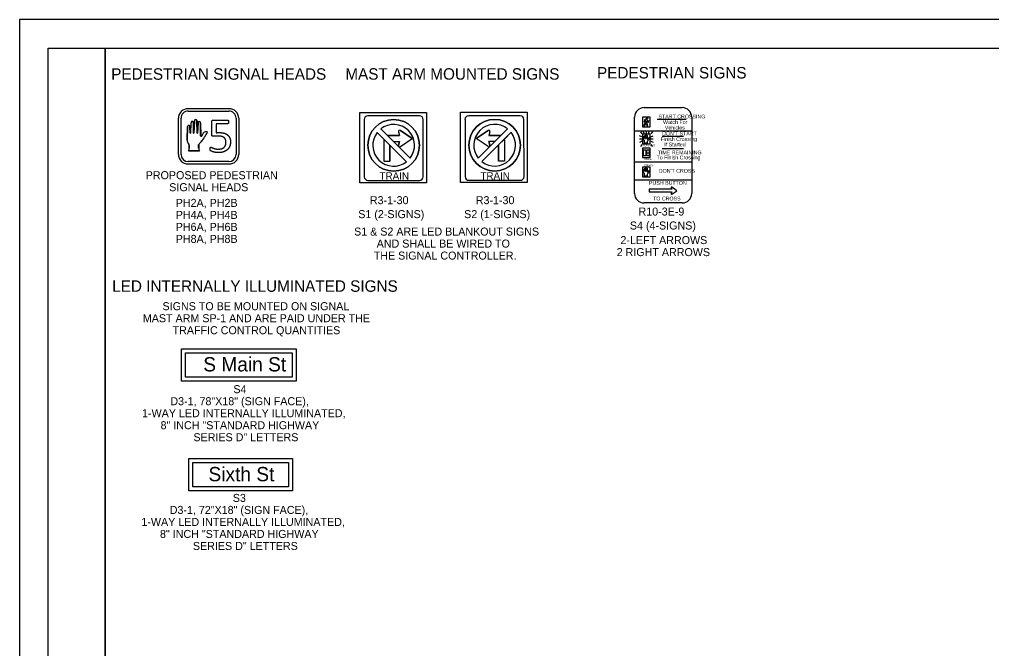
# Model space of a CAD drawing. Extents: x 0 to 34, y 0 to 22.
# Drawn here: x 0 to 17, y 11 to 22 of the extents above; entities that cross this region are included whole.
import ezdxf

# ---------------------------------------------------------------- set-up
doc = ezdxf.new("R2010")
doc.units = 0
for name, color, linetype in [('Default', 7, 'Continuous'), ('PM_P_Stop_Line', 7, 'Continuous'), ('SC_Scratch1', 7, 'Continuous'), ('SG_P_Conduit', 7, 'Continuous'), ('SG_P_Detection', 7, 'Continuous'), ('SG_P_Heads', 7, 'Continuous'), ('UT_X_Electric', 7, 'Continuous')]:
    doc.layers.add(name, color=color, linetype=linetype)

# ---------------------------------------------------------------- blocks, each defined once
blk = doc.blocks.new('HAND')
at = {"layer": 'Default'}
for points in [[(0.0005, 0.1047), (0.0004, 0.1045), (0.004, 0.1776), (0.004, 0.1776)], [(0.0186, 0.1776), (0.0186, 0.1776), (0.0199, 0.105), (0.0199, 0.105)], [(-0.0387, 0.0626), (-0.0387, 0.0626), (-0.0372, 0.143), (-0.0372, 0.143)], [(-0.0227, 0.143), (-0.0227, 0.143), (-0.0215, 0.105), (-0.0215, 0.105)], [(-0.0196, 0.1047), (-0.0197, 0.1045), (-0.0167, 0.1665), (-0.0167, 0.1665)], [(-0.0022, 0.1665), (-0.0022, 0.1665), (-0.0014, 0.105), (-0.0014, 0.105)], [(0.0218, 0.1047), (0.0218, 0.1045), (0.0247, 0.1659), (0.0247, 0.1659)], [(0.0392, 0.1659), (0.0392, 0.1659), (0.0402, 0.0888), (0.0402, 0.0888)], [(0.0477, 0.089), (0.0477, 0.089)], [(-0.032, 0.0432), (-0.032, 0.0432)], [(-0.0271, 0.0154), (-0.0271, 0.0154), (-0.0271, 0.0308), (-0.0271, 0.0308)], [(0.0284, 0.0364), (0.0284, 0.0364), (0.0284, 0.0154), (0.0284, 0.0154)], [(0.0327, -0.0008), (-0.0313, -0.0008), (-0.0313, -0.0008)], [(0.0327, -0.0008), (0.0327, -0.0008)]]:
    blk.add_lwpolyline(points, dxfattribs=at)
for centre, radius, start, end in [((-0.0094, 0.1665), 0.00726, 0, 180), ((0.0113, 0.1776), 0.00726, 0, 180), ((0.032, 0.1659), 0.00726, 0, 180), ((-0.03, 0.143), 0.00726, 0, 180), ((-0.011, 0.0613), 0.0278, 177.3964, 220.6574), ((-0.0206, 0.1048), 0.000943, 167.1401, 358.6099), ((-0.0005, 0.1048), 0.000943, 167.1401, 358.6099), ((0.0208, 0.1048), 0.000943, 167.1401, 358.6099), ((0.0439, 0.0907), 0.00414, 208.0703, 335.996), ((-0.1141, 0.1925), 0.2098, 318.2058, 337.3712), ((0.078, 0.0836), 0.0308, 107.2466, 169.8826), ((0.073, 0.1019), 0.0119, 56.229, 110.2726), ((-0.0476, 0.0298), 0.0205, 2.7749, 40.7212), ((-0.0593, 0.0151), 0.0322, 330.2887, 0.5181), ((0.0742, 0.0112), 0.0523, 127.5194, 151.0809), ((0.0606, 0.0151), 0.0322, 179.4819, 209.7113)]:
    blk.add_arc(centre, radius, start, end, dxfattribs=at)

msp = doc.modelspace()

# ---------------------------------------------------------------- linework, layer by layer
at = {"layer": 'PM_P_Stop_Line'}
for points in [[(0.5, 21.5), (1.5, 21.5), (1.5, 0.5), (0.5, 0.5)], [(1.5, 21.5), (33.5, 21.5), (33.5, 0.5), (1.5, 0.5)]]:
    msp.add_lwpolyline(points, close=True, dxfattribs=at)
at = {"layer": 'SC_Scratch1'}
for p, q in [((8.194, 20.06), (7.989, 19.919)), ((6.458, 19.971), (6.648, 19.971)), ((6.628, 20.034), (6.648, 19.971)), ((6.661, 20.058), (6.866, 19.917)), ((6.661, 19.776), (6.866, 19.917)), ((8.194, 19.778), (7.989, 19.919)), ((8.227, 20.036), (8.207, 19.973)), ((8.397, 19.973), (8.207, 19.973)), ((6.372, 19.885), (6.372, 19.52)), ((6.48, 19.803), (6.48, 19.52)), ((6.54, 19.863), (6.648, 19.863)), ((6.628, 19.8), (6.648, 19.863)), ((8.315, 19.866), (8.207, 19.866)), ((8.227, 19.802), (8.207, 19.866)), ((8.375, 19.805), (8.375, 19.522)), ((8.483, 19.887), (8.483, 19.522)), ((6.372, 19.52), (6.48, 19.52))]:
    msp.add_line(p, q, dxfattribs=at)
for points in [[(5.95, 20.375), (7.117, 20.375), (7.117, 19.144), (5.95, 19.144)], [(7.713, 20.377), (8.88, 20.377), (8.88, 19.147), (7.713, 19.147)], [(2.836, 16.242), (4.842, 16.242), (4.842, 15.677), (2.836, 15.677)], [(2.906, 16.172), (4.772, 16.172), (4.772, 15.747), (2.906, 15.747)], [(2.963, 14.323), (4.777, 14.323), (4.777, 13.758), (2.963, 13.758)], [(3.033, 14.253), (4.707, 14.253), (4.707, 13.828), (3.033, 13.828)]]:
    msp.add_lwpolyline(points, close=True, dxfattribs=at)
for points in [[(6.029, 20.25), (6.03, 19.25)], [(6.995, 20.314), (6.093, 20.314)], [(7.061, 19.25), (7.059, 20.25)], [(7.792, 20.252), (7.793, 19.252)], [(8.758, 20.317), (7.856, 20.317)], [(8.824, 19.252), (8.823, 20.252)], [(8.194, 19.778), (7.989, 19.919), (8.194, 20.06)], [(6.48, 19.803), (6.375, 19.907)], [(6.436, 19.968), (6.54, 19.863), (6.648, 19.863), (6.628, 19.8)], [(6.628, 20.034), (6.648, 19.971), (6.458, 19.971)], [(6.661, 19.776), (6.866, 19.917), (6.661, 20.058)], [(8.227, 20.036), (8.207, 19.973), (8.397, 19.973)], [(8.419, 19.97), (8.315, 19.866), (8.207, 19.866), (8.227, 19.802)], [(8.375, 19.805), (8.48, 19.909)], [(6.372, 19.885), (6.372, 19.52), (6.48, 19.52), (6.48, 19.803)], [(8.483, 19.887), (8.483, 19.522), (8.375, 19.522), (8.375, 19.805)], [(6.095, 19.185), (6.996, 19.185)], [(7.858, 19.187), (8.76, 19.187)]]:
    msp.add_lwpolyline(points, dxfattribs=at)
for centre, radius, start, end in [((6.093, 20.25), 0.0644, 90, 180), ((6.995, 20.25), 0.0644, 0, 90), ((7.856, 20.252), 0.0644, 90, 180), ((8.758, 20.252), 0.0644, 0, 90), ((6.649, 20.041), 0.0215, 55.4837, 197.3618), ((6.649, 20.041), 0.0215, 55.4837, 197.3618), ((8.206, 20.043), 0.0215, 342.6382, 124.5163), ((8.206, 20.043), 0.0215, 342.6382, 124.5163), ((6.458, 19.885), 0.0859, 165, 180), ((6.458, 19.885), 0.0859, 165, 180), ((6.458, 19.885), 0.0859, 90, 105), ((6.458, 19.885), 0.0859, 90, 105), ((8.397, 19.887), 0.0859, 75, 90), ((8.397, 19.887), 0.0859, 75, 90), ((8.397, 19.887), 0.0859, 360, 15), ((8.397, 19.887), 0.0859, 360, 15), ((6.649, 19.794), 0.0215, 162.6382, 304.5163), ((6.649, 19.794), 0.0215, 162.6382, 304.5163), ((8.206, 19.796), 0.0215, 235.4837, 17.3618), ((8.206, 19.796), 0.0215, 235.4837, 17.3618), ((6.095, 19.25), 0.0644, 180, 270), ((6.996, 19.25), 0.0644, 270, 0), ((7.858, 19.252), 0.0644, 180, 270), ((8.76, 19.252), 0.0644, 270, 0)]:
    msp.add_arc(centre, radius, start, end, dxfattribs=at)
at = {"layer": 'SG_P_Conduit'}
for p, q in [((10.928, 20.244), (10.925, 20.209)), ((10.933, 20.209), (10.937, 20.239)), ((10.937, 20.239), (10.946, 20.239)), ((10.946, 20.239), (10.941, 20.223)), ((10.983, 20.231), (10.983, 20.231)), ((11.007, 20.213), (10.983, 20.231)), ((11.155, 20.255), (11.657, 20.255)), ((10.942, 20.202), (10.921, 20.14)), ((10.921, 20.14), (10.931, 20.132)), ((10.925, 20.209), (10.933, 20.209)), ((10.931, 20.132), (10.955, 20.186)), ((10.941, 20.204), (10.942, 20.202)), ((10.955, 20.186), (10.964, 20.175)), ((10.964, 20.175), (10.976, 20.133)), ((10.966, 20.211), (10.973, 20.227)), ((10.971, 20.2), (10.966, 20.211)), ((10.978, 20.184), (10.971, 20.2)), ((10.973, 20.227), (10.979, 20.217)), ((10.976, 20.133), (10.988, 20.139)), ((10.988, 20.139), (10.978, 20.184)), ((10.979, 20.217), (11.002, 20.206)), ((11.002, 20.206), (11.007, 20.213)), ((6.257, 20.025), (6.77, 19.512)), ((8.598, 20.027), (8.085, 19.514)), ((10.757, 20.055), (11.757, 20.055)), ((10.885, 19.946), (10.845, 19.965)), ((10.885, 19.909), (10.845, 19.909)), ((10.858, 20.037), (10.886, 20.002)), ((10.91, 20.042), (10.926, 20.002)), ((10.922, 19.887), (10.924, 19.96)), ((10.933, 19.96), (10.935, 19.921)), ((10.935, 19.921), (10.939, 19.921)), ((10.939, 19.921), (10.94, 19.973)), ((10.95, 19.973), (10.95, 19.921)), ((10.95, 19.921), (10.953, 19.921)), ((10.953, 19.921), (10.955, 19.98)), ((10.964, 20.002), (10.964, 20.042)), ((10.966, 19.98), (10.966, 19.921)), ((10.966, 19.921), (10.97, 19.921)), ((10.97, 19.921), (10.971, 19.972)), ((10.98, 19.973), (10.983, 19.904)), ((10.989, 19.904), (11.001, 19.922)), ((11, 20.002), (11.015, 20.042)), ((11.069, 20.037), (11.041, 20.002)), ((11.042, 19.945), (11.082, 19.963)), ((11.082, 19.909), (11.042, 19.909)), ((11.241, 19.959), (11.615, 19.959)), ((10.885, 19.87), (10.845, 19.851)), ((10.885, 19.813), (10.858, 19.781)), ((10.979, 19.836), (10.93, 19.836)), ((10.933, 19.842), (10.933, 19.866)), ((10.975, 19.864), (10.975, 19.843)), ((11.042, 19.872), (11.082, 19.853)), ((11.042, 19.813), (11.069, 19.781)), ((11.241, 19.742), (11.615, 19.742)), ((10.973, 19.669), (11.013, 19.669)), ((10.757, 19.513), (11.757, 19.513)), ((10.922, 19.311), (10.924, 19.384)), ((10.933, 19.384), (10.935, 19.346)), ((10.939, 19.346), (10.94, 19.397)), ((10.95, 19.397), (10.95, 19.346)), ((10.953, 19.346), (10.955, 19.404)), ((10.966, 19.404), (10.966, 19.346)), ((10.97, 19.346), (10.971, 19.397)), ((10.98, 19.397), (10.983, 19.329)), ((10.979, 19.26), (10.93, 19.26)), ((10.933, 19.266), (10.933, 19.291)), ((10.935, 19.346), (10.939, 19.346)), ((10.95, 19.346), (10.953, 19.346)), ((10.966, 19.346), (10.97, 19.346)), ((10.975, 19.289), (10.975, 19.268)), ((10.989, 19.328), (11.001, 19.347)), ((10.757, 19.194), (11.757, 19.194)), ((11.397, 19.058), (11.406, 19.03)), ((11.499, 19.006), (11.411, 19.068)), ((11.405, 19.03), (11.015, 19.03)), ((11.015, 19.03), (11.015, 18.983)), ((11.257, 19.006), (11.257, 19.006)), ((11.406, 18.983), (11.397, 18.954)), ((11.406, 19.03), (11.405, 19.03)), ((11.411, 18.944), (11.499, 19.006))]:
    msp.add_line(p, q, dxfattribs=at)
for points in [[(10.924, 20.458), (11.59, 20.458)], [(10.757, 18.958), (10.757, 20.291)], [(11.757, 20.291), (11.757, 18.958)], [(6.436, 19.968), (6.318, 20.086)], [(8.419, 19.97), (8.537, 20.088)], [(6.257, 20.025), (6.375, 19.907)], [(6.375, 19.907), (6.48, 19.803), (6.77, 19.512)], [(6.831, 19.573), (6.54, 19.863), (6.436, 19.968)], [(8.024, 19.575), (8.315, 19.866), (8.419, 19.97)], [(8.48, 19.909), (8.375, 19.805), (8.085, 19.514)], [(8.598, 20.027), (8.48, 19.909)], [(11.018, 19.927), (11.008, 19.908), (11, 19.894)], [(11.018, 19.352), (11.008, 19.332), (11, 19.319)], [(11.015, 18.983), (11.405, 18.983)], [(11.59, 18.791), (10.924, 18.791)]]:
    msp.add_lwpolyline(points, dxfattribs=at)
for points in [[(10.895, 20.124), (11.032, 20.124), (11.032, 20.291), (10.895, 20.291)], [(10.895, 19.826), (11.032, 19.826), (11.032, 19.992), (10.895, 19.992)], [(10.895, 19.584), (11.032, 19.584), (11.032, 19.751), (10.895, 19.751)], [(10.912, 19.723), (10.952, 19.723), (10.952, 19.615), (10.912, 19.615)], [(10.973, 19.723), (11.013, 19.723), (11.013, 19.615), (10.973, 19.615)], [(10.895, 19.25), (11.032, 19.25), (11.032, 19.417), (10.895, 19.417)]]:
    msp.add_lwpolyline(points, close=True, dxfattribs=at)
for centre, radius in [((6.544, 19.799), 0.451), ((8.311, 19.801), 0.451), ((10.976, 20.271), 0.0103)]:
    msp.add_circle(centre, radius, dxfattribs=at)
for centre, radius, start, end in [((10.924, 20.291), 0.167, 90, 180), ((11.59, 20.291), 0.167, 0, 90), ((6.544, 19.799), 0.451, 0, 180), ((8.311, 19.801), 0.451, 360, 180), ((6.544, 19.799), 0.365, 321.7563, 128.2437), ((6.544, 19.799), 0.365, 321.7563, 128.2437), ((8.311, 19.801), 0.365, 51.7563, 218.2437), ((8.311, 19.801), 0.365, 51.7563, 218.2437), ((6.544, 19.799), 0.365, 141.7563, 308.2437), ((6.544, 19.799), 0.365, 141.7563, 308.2437), ((8.311, 19.801), 0.365, 231.7563, 38.2437), ((8.311, 19.801), 0.365, 231.7563, 38.2437), ((10.929, 19.958), 0.00491, 17.2617, 162.7383), ((10.945, 19.972), 0.00492, 8.2338, 172.7854), ((10.96, 19.979), 0.00538, 14.8098, 166.7635), ((10.975, 19.972), 0.00484, 7.5404, 176.7973), ((10.986, 19.906), 0.00319, 202.4359, 334.4764), ((10.961, 19.916), 0.0451, 307.7756, 331.4618), ((11.011, 19.916), 0.012, 86.7688, 149.658), ((11.012, 19.904), 0.0246, 76.4727, 90.8564), ((6.544, 19.799), 0.451, 180, 0), ((8.311, 19.801), 0.451, 180, 360), ((10.934, 19.886), 0.0115, 175.876, 235.3646), ((10.917, 19.864), 0.0162, 6.5622, 49.5415), ((10.922, 19.844), 0.0104, 311.3432, 350.588), ((11.001, 19.856), 0.0266, 117.1684, 162.5699), ((10.986, 19.844), 0.011, 181.2383, 225.3799), ((10.929, 19.383), 0.00491, 17.2617, 162.7383), ((10.945, 19.397), 0.00492, 8.2338, 172.7854), ((10.96, 19.403), 0.00538, 14.8098, 166.7635), ((10.975, 19.397), 0.00484, 7.5404, 176.7973), ((10.934, 19.311), 0.0115, 175.876, 235.3646), ((10.917, 19.289), 0.0162, 6.5622, 49.5415), ((10.922, 19.268), 0.0104, 311.3432, 350.588), ((11.001, 19.281), 0.0266, 117.1684, 162.5699), ((10.986, 19.268), 0.011, 181.2383, 225.3799), ((10.986, 19.33), 0.00319, 202.4359, 334.4764), ((10.961, 19.34), 0.0451, 307.7756, 331.4618), ((11.011, 19.341), 0.012, 86.7688, 149.658), ((11.012, 19.328), 0.0246, 76.4727, 90.8564), ((11.405, 19.061), 0.00912, 54.9207, 197.6378), ((10.924, 18.958), 0.167, 180, 270), ((11.405, 18.951), 0.00912, 162.3622, 305.0792), ((11.59, 18.958), 0.167, 270, 0)]:
    msp.add_arc(centre, radius, start, end, dxfattribs=at)
for points in [[(10.971, 20.259), (10.971, 20.259), (10.968, 20.259), (10.965, 20.259), (10.963, 20.259), (10.961, 20.259), (10.956, 20.256), (10.939, 20.249), (10.928, 20.244)], [(10.946, 20.239), (10.944, 20.234), (10.942, 20.228), (10.94, 20.22), (10.939, 20.214), (10.938, 20.209), (10.94, 20.206), (10.941, 20.204)], [(10.983, 20.231), (10.982, 20.238), (10.979, 20.245), (10.977, 20.253), (10.972, 20.258), (10.971, 20.259)]]:
    msp.add_open_spline(points, degree=3, dxfattribs=at)
at = {"layer": 'SG_P_Detection'}
for p, q in [((2.949, 20.44), (3.665, 20.44)), ((2.78, 19.641), (2.78, 20.271)), ((2.826, 19.641), (2.826, 20.271)), ((2.953, 20.397), (3.661, 20.397)), ((3.39, 20.241), (3.64, 20.241)), ((3.788, 20.271), (3.788, 19.641)), ((3.834, 20.271), (3.834, 19.641)), ((3.364, 19.984), (3.364, 20.212)), ((3.691, 19.86), (3.691, 19.86)), ((3.665, 19.472), (2.949, 19.472)), ((3.661, 19.515), (2.953, 19.515))]:
    msp.add_line(p, q, dxfattribs=at)
for points in [[(2.939, 20.125), (2.935, 19.888)], [(2.986, 20.013), (2.982, 20.125), (2.982, 20.125)], [(3, 20.195), (2.991, 20.012), (2.991, 20.012)], [(3.046, 20.013), (3.043, 20.195), (3.043, 20.195)], [(3.062, 20.227), (3.051, 20.012), (3.051, 20.012)], [(3.109, 20.013), (3.105, 20.227)], [(3.123, 20.193), (3.114, 20.012), (3.114, 20.012)], [(3.169, 19.965), (3.166, 20.193)], [(3.64, 20.176), (3.439, 20.176), (3.439, 20.018)], [(2.991, 20.012), (2.991, 20.012), (2.991, 20.012)], [(3.051, 20.012), (3.051, 20.012), (3.051, 20.012)], [(3.114, 20.012), (3.114, 20.012), (3.114, 20.012)], [(3.191, 19.966), (3.191, 19.966)], [(2.955, 19.83), (2.955, 19.831)], [(2.969, 19.794), (2.969, 19.748)], [(3.134, 19.748), (3.134, 19.811)], [(2.957, 19.7), (3.147, 19.7)]]:
    msp.add_lwpolyline(points, dxfattribs=at)
for centre, major_axis, start_param, end_param in [((2.949, 20.271), (0.169, 0), 1.570796, 3.141593), ((3.665, 20.271), (0.169, 0), 6.283185, 7.853982), ((2.953, 20.271), (0.127, 0), 1.570796, 3.141593), ((3.083, 20.227), (0.0215, 0), 6.283185, 9.424778), ((3.661, 20.271), (0.127, 0), 6.283185, 7.853982), ((2.961, 20.125), (0.0215, 0), 0, 3.141593), ((3.022, 20.195), (0.0215, 0), 0, 3.141593), ((3.145, 20.193), (0.0215, 0), 0, 3.141593), ((2.989, 20.012), (0.0028, 0), 2.917145, 6.054008), ((2.989, 20.012), (0.0028, 0), 6.061637, 6.258923), ((3.048, 20.012), (0.0028, 0), 2.917145, 6.049226), ((3.048, 20.012), (0.0028, 0), 6.126272, 6.258923), ((3.112, 20.012), (0.0028, 0), 2.917145, 6.058743), ((3.112, 20.012), (0.0028, 0), 6.099269, 6.258923), ((3.18, 19.971), (0.0123, 0), 3.631512, 5.864236), ((2.711, 20.271), (0.623, 0), 5.553739, 5.888238), ((3.281, 19.95), (0.0914, 0), 1.871807, 2.965011), ((3.266, 20.004), (0.0353, 0), 0.981382, 1.92462), ((3.017, 19.884), (0.0825, 0), 3.096152, 3.851198), ((2.909, 19.791), (0.0609, 0), 0.048431, 0.710719), ((2.874, 19.748), (0.0956, 0), 5.764626, 6.292228), ((3.27, 19.736), (0.155, 0), 2.225634, 2.636859), ((3.23, 19.748), (0.0956, 0), 3.13255, 3.660152), ((2.949, 19.641), (0.169, 0), 3.141593, 4.712389), ((2.953, 19.641), (0.127, 0), 3.141593, 4.712389), ((3.661, 19.641), (0.127, 0), 4.712389, 6.283185), ((3.665, 19.641), (0.169, 0), 4.712389, 6.283185)]:
    msp.add_ellipse(centre, major_axis=major_axis, ratio=0.995332, start_param=start_param, end_param=end_param, dxfattribs=at)
for points in [[(3.364, 20.212), (3.364, 20.227), (3.371, 20.234)], [(3.371, 20.234), (3.378, 20.241), (3.39, 20.241)], [(3.64, 20.241), (3.643, 20.241), (3.646, 20.239)], [(3.646, 20.239), (3.65, 20.237), (3.652, 20.233)], [(3.652, 20.233), (3.654, 20.229), (3.655, 20.223)], [(3.652, 20.184), (3.648, 20.176), (3.64, 20.176)], [(3.656, 20.209), (3.656, 20.193), (3.652, 20.184)], [(3.655, 20.223), (3.656, 20.217), (3.656, 20.209)], [(3.37, 19.962), (3.364, 19.968), (3.364, 19.984)], [(3.387, 19.957), (3.375, 19.957), (3.37, 19.962)], [(3.423, 19.959), (3.404, 19.957), (3.387, 19.957)], [(3.468, 19.962), (3.442, 19.962), (3.423, 19.959)], [(3.439, 20.018), (3.454, 20.02), (3.469, 20.021)], [(3.533, 19.955), (3.506, 19.962), (3.468, 19.962)], [(3.469, 20.021), (3.485, 20.021), (3.505, 20.021)], [(3.505, 20.021), (3.551, 20.021), (3.586, 20.01)], [(3.577, 19.935), (3.56, 19.948), (3.533, 19.955)], [(3.604, 19.9), (3.595, 19.921), (3.577, 19.935)], [(3.586, 20.01), (3.621, 19.998), (3.644, 19.977)], [(3.612, 19.853), (3.612, 19.88), (3.604, 19.9)], [(3.644, 19.977), (3.667, 19.956), (3.679, 19.926)], [(3.679, 19.926), (3.691, 19.896), (3.691, 19.86)], [(3.336, 19.751), (3.337, 19.757), (3.339, 19.76)], [(3.336, 19.738), (3.336, 19.745), (3.336, 19.751)], [(3.336, 19.724), (3.336, 19.73), (3.336, 19.738)], [(3.338, 19.715), (3.336, 19.718), (3.336, 19.724)], [(3.339, 19.76), (3.34, 19.764), (3.343, 19.766)], [(3.343, 19.766), (3.345, 19.767), (3.348, 19.767)], [(3.348, 19.767), (3.353, 19.767), (3.362, 19.762)], [(3.362, 19.762), (3.371, 19.757), (3.386, 19.75)], [(3.386, 19.75), (3.402, 19.744), (3.425, 19.738)], [(3.425, 19.738), (3.448, 19.733), (3.479, 19.733)], [(3.479, 19.733), (3.508, 19.733), (3.532, 19.739)], [(3.532, 19.739), (3.557, 19.746), (3.574, 19.761)], [(3.633, 19.72), (3.605, 19.696), (3.567, 19.684)], [(3.574, 19.761), (3.592, 19.776), (3.602, 19.798)], [(3.602, 19.798), (3.612, 19.821), (3.612, 19.853)], [(3.676, 19.78), (3.661, 19.744), (3.633, 19.72)], [(3.691, 19.86), (3.691, 19.815), (3.676, 19.78)], [(3.34, 19.708), (3.339, 19.711), (3.338, 19.715)], [(3.345, 19.703), (3.341, 19.706), (3.34, 19.708)], [(3.36, 19.695), (3.348, 19.7), (3.345, 19.703)], [(3.39, 19.684), (3.371, 19.689), (3.36, 19.695)], [(3.431, 19.675), (3.408, 19.679), (3.39, 19.684)], [(3.481, 19.671), (3.455, 19.671), (3.431, 19.675)], [(3.567, 19.684), (3.528, 19.671), (3.481, 19.671)]]:
    msp.add_open_spline(points, degree=2, dxfattribs=at)
at = {"layer": 'SG_P_Heads'}
msp.add_lwpolyline([(0, 0), (34, 0), (34, 22), (0, 22)], close=True, dxfattribs=at)

# ---------------------------------------------------------------- block references
at = {"layer": 'SG_P_Detection', "xscale": 2.9676009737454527, "yscale": 2.953749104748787, "rotation": -4.08392135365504e-09}
msp.add_blockref('HAND', (3.05, 19.703), dxfattribs=at)

# ---------------------------------------------------------------- texts
at = {"layer": 'SC_Scratch1'}
for s, height, p in [('TRAIN', 0.1288, (6.297, 19.198)), ('TRAIN', 0.1288, (8.061, 19.2)), ('SIGNS TO BE MOUNTED ON SIGNAL ', 0.14, (2.502, 16.916)), ('MAST ARM SP-1 AND ARE PAID UNDER THE ', 0.14, (2.158, 16.706)), ('TRAFFIC CONTROL QUANTITIES', 0.14, (2.678, 16.496)), ('S Main St', 0.25, (3.215, 15.845)), ('S4', 0.14, (3.741, 15.465)), ('D3-1, 78"X18" (SIGN FACE),', 0.14, (2.639, 15.255)), ('1-WAY LED INTERNALLY ILLUMINATED, ', 0.14, (2.144, 15.045)), ('8" INCH "STANDARD HIGHWAY', 0.14, (2.468, 14.835)), (' SERIES D" LETTERS', 0.14, (2.991, 14.625)), ('Sixth St', 0.25, (3.306, 13.925)), ('S3', 0.14, (3.731, 13.564)), ('D3-1, 72"X18" (SIGN FACE),', 0.14, (2.628, 13.354)), ('1-WAY LED INTERNALLY ILLUMINATED, ', 0.14, (2.133, 13.144)), ('8" INCH "STANDARD HIGHWAY', 0.14, (2.458, 12.934)), (' SERIES D" LETTERS', 0.14, (2.981, 12.724))]:
    msp.add_text(s, height=height, dxfattribs=at).set_placement(p)
at = {"layer": 'SG_P_Conduit'}
for s, height, p in [('START CROSSING', 0.06667, (11.176, 20.269)), ('Watch For', 0.0667, (11.255, 20.172)), ('Vehicles', 0.0667, (11.287, 20.075)), ('Finish Crossing', 0.06667, (11.213, 19.874)), ("DON'T START", 0.06667, (11.24, 19.973)), ('FLASHING', 0.0311, (10.903, 19.784)), ('If Started', 0.0667, (11.277, 19.78)), ('TIMER', 0.0311, (10.923, 19.543)), ('To Finish Crossing', 0.06667, (11.142, 19.553)), ('TIME REMAINING', 0.06667, (11.162, 19.641)), ('STEADY', 0.0311, (10.918, 19.43)), ("DON'T CROSS", 0.06667, (11.181, 19.32)), ('PUSH BUTTON', 0.06667, (11.01, 19.109)), ('TO CROSS', 0.0667, (11.081, 18.835))]:
    msp.add_text(s, height=height, dxfattribs=at).set_placement(p)
at = {"layer": 'UT_X_Electric'}
for s, height, p in [('PEDESTRIAN SIGNAL HEADS', 0.2, (1.605, 20.946)), ('MAST ARM MOUNTED SIGNS', 0.2, (5.699, 20.947)), ('PEDESTRIAN SIGNS', 0.2, (10.1, 20.968)), ('PROPOSED PEDESTRIAN ', 0.14, (2.208, 19.207)), ('SIGNAL HEADS ', 0.14, (2.619, 18.997)), ('R3-1-30', 0.14, (6.128, 18.77)), ('R3-1-30', 0.14, (7.98, 18.77)), ('PH2A, PH2B', 0.14, (2.733, 18.723)), ('R10-3E-9', 0.14, (10.826, 18.571)), ('PH4A, PH4B', 0.14, (2.733, 18.513)), ('S1 (2-SIGNS)', 0.14, (5.925, 18.526)), ('S2 (1-SIGNS)', 0.14, (7.777, 18.526)), ('PH6A, PH6B', 0.14, (2.733, 18.303)), (' S1 & S2 ARE LED BLANKOUT SIGNS', 0.14, (5.8, 18.221)), ('S4 (4-SIGNS)', 0.14, (10.675, 18.327)), ('PH8A, PH8B', 0.14, (2.733, 18.093)), ('2-LEFT ARROWS', 0.14, (10.51, 18.072)), ('AND SHALL BE WIRED TO ', 0.14, (6.247, 18.011)), ('THE SIGNAL CONTROLLER.', 0.14, (6.196, 17.801)), ('2 RIGHT ARROWS', 0.14, (10.444, 17.862)), ('LED INTERNALLY ILLUMINATED SIGNS', 0.2, (1.622, 17.238))]:
    msp.add_text(s, height=height, dxfattribs=at).set_placement(p)

doc.saveas('drawing.dxf')
